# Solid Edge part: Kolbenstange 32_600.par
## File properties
Username: ahadarics
Dokumentum tartalom típus: 0
Author: ahadarics
Last saved by: ahadarics
Revision: 93
Sűrűség: 0,000 kg/m^3
Pontosság: 0,990
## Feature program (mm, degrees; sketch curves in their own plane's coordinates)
base feature "unnamed BaseFeature 1"
thread "unnamed Thread 1"
chamfer "Letörés_1"  SetBackValue2 = 20 deg
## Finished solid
Body 1: solid body, 19 faces, 27 edges, 11 vertices.
  Faces by surface: plane 8, cylinder 5, cone 3, torus 3
  Edges by curve: circle 15, line 7, curve on surface 3, ellipse 2
Bounding box of the edges (mm; curved faces can reach further): 32.000 x 32.000 x 715.500, from (-16, -16, -50.25) to (16, 16, 665.25).
Cylindrical faces by radius (mm): R3.95 x1, R5 x1, R5.8 x1, R6 x1, R16 x1
Conical faces (half-angle, radius in mm at the cone's reference point): 20 deg R5 x1, 30 deg R5.9 x1, 60 deg R4.475 x1
Toroidal faces (ring radius, tube radius in mm): R4.35 r0.4 x2, R4.6 r1.2 x1
Planar faces by outward normal: +x 1, +z 3, -x 1, -z 1, oblique 2
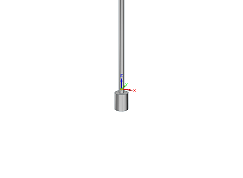
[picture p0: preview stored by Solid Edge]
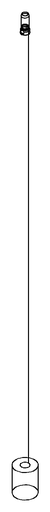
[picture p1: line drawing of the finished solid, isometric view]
